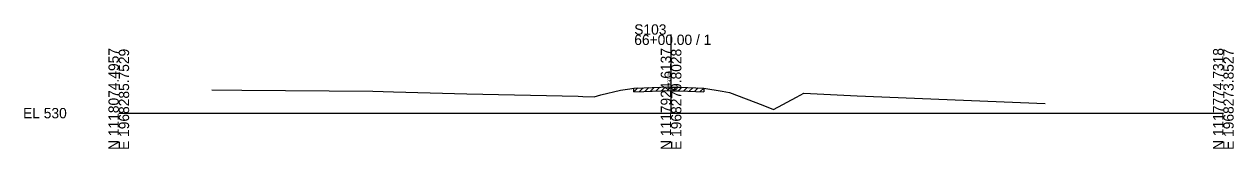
# Model space of a CAD drawing. Extents: x 974 to 1303, y 990 to 14518.
# Drawn here: x 974.3 to 1302.8, y 9490.3 to 9524.2 of the extents above; entities that cross this region are included whole.
import ezdxf

# ---------------------------------------------------------------- set-up
doc = ezdxf.new("R2010")
doc.units = 0
for name, color, linetype in [('Level 10', 7, 'Continuous'), ('Level 60', 7, 'Continuous'), ('Level 61', 7, 'Continuous'), ('Level 63', 7, 'Continuous')]:
    doc.layers.add(name, color=color, linetype=linetype)

msp = doc.modelspace()

# ---------------------------------------------------------------- linework, layer by layer
at = {"layer": 'Level 60'}
for p, q in [((1025.25, 9506.29), (1033.38, 9506.26)), ((1033.38, 9506.26), (1069.02, 9505.95)), ((1069.02, 9505.95), (1074.61, 9505.82)), ((1074.61, 9505.82), (1094.5, 9505.29)), ((1094.5, 9505.29), (1124.79, 9504.58)), ((1124.79, 9504.58), (1125.99, 9504.48)), ((1125.99, 9504.48), (1129.07, 9504.43)), ((1129.07, 9504.43), (1130.95, 9504.95)), ((1130.95, 9504.95), (1136.22, 9506.21)), ((1136.22, 9506.21), (1138.8, 9506.64)), ((1138.8, 9506.64), (1139.9, 9506.82)), ((1139.9, 9506.82), (1142.64, 9506.91)), ((1142.64, 9506.91), (1149.46, 9507.11)), ((1149.46, 9507.11), (1150, 9507.09)), ((1150, 9507.09), (1152.42, 9507.02)), ((1152.42, 9507.02), (1158.9, 9506.83)), ((1158.9, 9506.83), (1163.92, 9505.98)), ((1163.92, 9505.98), (1165.87, 9505.62)), ((1165.87, 9505.62), (1174.94, 9502.15)), ((1184.09, 9504.33), (1186.07, 9505.41)), ((1186.07, 9505.41), (1200.51, 9504.66)), ((1200.51, 9504.66), (1251.58, 9502.64)), ((1174.94, 9502.15), (1177.86, 9500.98)), ((1177.86, 9500.98), (1184.09, 9504.33))]:
    msp.add_line(p, q, dxfattribs=at)
at = {"layer": 'Level 61'}
for p, q in [((1139.9, 9505.82), (1140.94, 9506.85)), ((1139.9, 9505.82), (1139.9, 9506.82)), ((1139.9, 9505.82), (1142.64, 9505.91)), ((1139.9, 9505.82), (1139.9, 9505.82)), ((1141.4, 9505.87), (1142.44, 9506.9)), ((1142.64, 9505.91), (1149.46, 9506.11)), ((1142.9, 9505.92), (1143.93, 9506.95)), ((1144.4, 9505.96), (1145.43, 9506.99)), ((1145.9, 9506.01), (1146.93, 9507.04)), ((1147.4, 9506.05), (1148.43, 9507.08)), ((1148.9, 9506.09), (1149.9, 9507.1)), ((1149.46, 9506.11), (1150, 9506.09)), ((1150, 9506.09), (1152.42, 9506.02)), ((1150.4, 9506.08), (1151.37, 9507.05)), ((1151.9, 9506.03), (1152.87, 9507)), ((1152.42, 9506.02), (1158.9, 9505.83)), ((1153.4, 9505.99), (1154.37, 9506.96)), ((1154.9, 9505.94), (1155.87, 9506.92)), ((1156.4, 9505.9), (1157.37, 9506.87)), ((1157.9, 9505.86), (1158.87, 9506.83)), ((1158.9, 9506.83), (1158.9, 9505.83))]:
    msp.add_line(p, q, dxfattribs=at)
at = {"layer": 'Level 63'}
for p, q in [((1150, 9500), (1150, 9521.33)), ((1000, 9500), (1150, 9500)), ((1150, 9500), (1300, 9500))]:
    msp.add_line(p, q, dxfattribs=at)

# ---------------------------------------------------------------- texts
at = {"layer": 'Level 10'}
msp.add_text('537.09', height=0.9, rotation=90, dxfattribs=at).set_placement((1149.95, 9507.59))
at = {"layer": 'Level 63'}
for s, p in [('S103', (1140, 9521.33)), ('66+00.00 / 1', (1140, 9518.53)), ('EL 530', (974, 9498.6))]:
    msp.add_text(s, height=2.8, dxfattribs=at).set_placement(p)
for s, p in [('N 1118074.4957', (1000, 9490)), ('E 1968285.7529', (1002.8, 9490)), ('N 1117924.6137', (1150, 9490)), ('E 1968279.8028', (1152.8, 9490)), ('N 1117774.7318', (1300, 9490)), ('E 1968273.8527', (1302.8, 9490))]:
    msp.add_text(s, height=2.8, rotation=90, dxfattribs=at).set_placement(p)

doc.saveas('drawing.dxf')
